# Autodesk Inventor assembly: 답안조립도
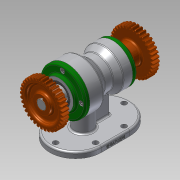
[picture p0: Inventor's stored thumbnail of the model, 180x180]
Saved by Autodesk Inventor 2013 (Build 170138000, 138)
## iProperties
Created: 2020-01
Part Number: 답안조립도
Document SubType Name: Assembly
Designer: Administrator
Author: Administrator
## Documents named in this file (13)
- C:\Users\Administrator\Desktop\700104V1012\답안조립도.iam
- C:\Users\Administrator\Desktop\700104V1012\본체.ipt
- C:\Users\Administrator\Desktop\700104V1012\뒤커버.ipt
- C:\Users\Administrator\Desktop\700104V1012\멈춤나사 M3.ipt
- C:\Users\Administrator\Desktop\700104V1012\베어링 6203.ipt
- C:\Users\Administrator\Desktop\700104V1012\베어링 6205.ipt
- C:\Users\Administrator\Desktop\700104V1012\볼트 M4.ipt
- C:\Users\Administrator\Desktop\700104V1012\스퍼기어.ipt
- C:\Users\Administrator\Desktop\700104V1012\앞커버.ipt
- C:\Users\Administrator\Desktop\700104V1012\오일 실 17 30 8.ipt
- C:\Users\Administrator\Desktop\700104V1012\오일 실 25 38 8.ipt
- C:\Users\Administrator\Desktop\700104V1012\축.ipt
- C:\Users\Administrator\Desktop\700104V1012\키 5 x 5 x 18.ipt
